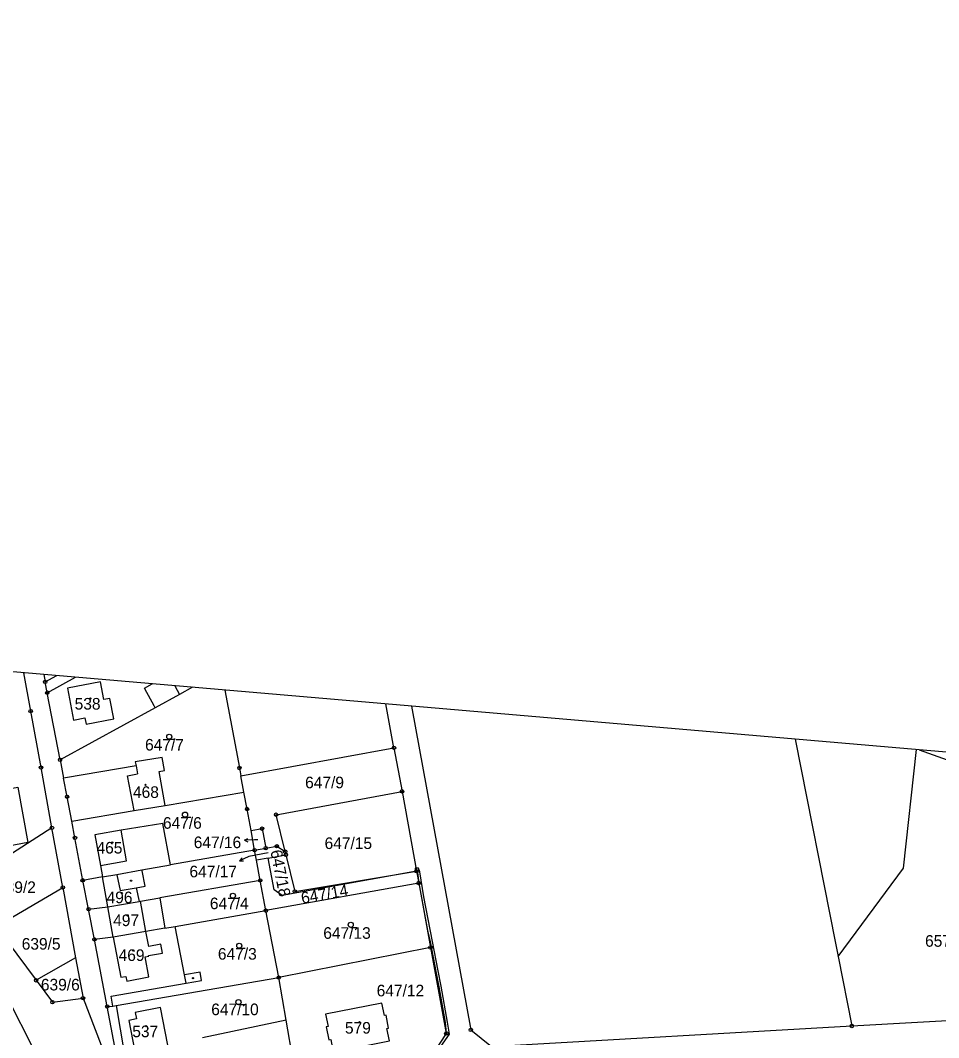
# Model space of a CAD drawing. Extents: x -537341 to -532984, y -1143469 to -1141314.
# Drawn here: x -533804.5 to -533535.5, y -1142913.3 to -1142615.3 of the extents above; entities that cross this region are included whole.
import ezdxf

# ---------------------------------------------------------------- set-up
doc = ezdxf.new("R2010")
doc.units = 0
for name, color, linetype in [('Hranice parcel', 7, 'Continuous'), ('parcelní_č_2000', 7, 'Continuous'), ('Pop  PČ popisy', 7, 'Continuous'), ('Vnitřní kresba', 7, 'Continuous'), ('Věcná břemena k části', 7, 'Continuous'), ('x_formát_rám', 7, 'Continuous'), ('Značky bodu BP', 7, 'Continuous'), ('Značky budov', 7, 'Continuous'), ('Značky kultur', 7, 'Continuous')]:
    doc.layers.add(name, color=color, linetype=linetype)

msp = doc.modelspace()

# ---------------------------------------------------------------- linework, layer by layer
at = {"layer": 'Hranice parcel'}
for p, q in [((-533796.62, -1142812.22), (-533797.23, -1142809.07)), ((-533796.62, -1142812.22), (-533788.31, -1142807.7)), ((-533792.86, -1142831.88), (-533796.62, -1142812.22)), ((-533739.9, -1142836.53), (-533695.03, -1142828.35)), ((-533695.03, -1142828.35), (-533692.68, -1142841.12)), ((-533792.86, -1142831.88), (-533791.82, -1142837.3)), ((-533738.99, -1142841.39), (-533739.9, -1142836.53)), ((-533762.1, -1142845.26), (-533738.99, -1142841.39)), ((-533692.68, -1142841.12), (-533688.43, -1142864.53)), ((-533795.23, -1142851.81), (-533820.96, -1142868.21)), ((-533792.04, -1142869.27), (-533795.23, -1142851.81)), ((-533736.91, -1142852.6), (-533733.68, -1142852.04)), ((-533735.85, -1142858.34), (-533736.91, -1142852.6)), ((-533733.68, -1142852.04), (-533732.6, -1142857.76)), ((-533735.85, -1142858.34), (-533732.6, -1142857.76)), ((-533735.85, -1142858.34), (-533760.5, -1142862.67)), ((-533735.3, -1142861.3), (-533735.85, -1142858.34)), ((-533731.85, -1142860.66), (-533735.3, -1142861.3)), ((-533731.85, -1142860.66), (-533726.7, -1142859.71)), ((-533726.92, -1142858.78), (-533726.7, -1142859.71)), ((-533734.2, -1142867.2), (-533735.3, -1142861.3)), ((-533780.43, -1142866.18), (-533786.23, -1142867.19)), ((-533688.43, -1142864.53), (-533687.8, -1142867.97)), ((-533811.62, -1142880.72), (-533792.04, -1142869.27)), ((-533792.04, -1142869.27), (-533788.29, -1142889.85)), ((-533784.49, -1142875.64), (-533786.23, -1142867.19)), ((-533734.2, -1142867.2), (-533763.65, -1142872.3)), ((-533732.56, -1142876.06), (-533734.2, -1142867.2)), ((-533687.8, -1142867.97), (-533732.56, -1142876.06)), ((-533687.8, -1142867.97), (-533684.34, -1142886.86)), ((-533763.65, -1142872.3), (-533762.13, -1142881.2)), ((-533782.79, -1142884.49), (-533784.49, -1142875.64)), ((-533759.14, -1142880.69), (-533732.56, -1142876.06)), ((-533728.79, -1142895.67), (-533732.56, -1142876.06)), ((-533811.62, -1142880.72), (-533799.87, -1142896.47)), ((-533762.13, -1142881.2), (-533759.14, -1142880.69)), ((-533779.04, -1142904.13), (-533782.79, -1142884.49)), ((-533684.34, -1142886.86), (-533728.79, -1142895.67)), ((-533788.29, -1142889.85), (-533799.87, -1142896.47)), ((-533788.29, -1142889.85), (-533786.13, -1142901.71)), ((-533564.92, -1142889.45), (-533560.9, -1142909.85)), ((-533776.44, -1142903.87), (-533728.79, -1142895.67)), ((-533726.64, -1142908.16), (-533728.79, -1142895.67)), ((-533800.6, -1142916.51), (-533807.97, -1142902.05)), ((-533786.13, -1142901.71), (-533773.02, -1142935.56)), ((-533779.04, -1142904.13), (-533777.37, -1142904.03)), ((-533773.02, -1142935.56), (-533779.04, -1142904.13)), ((-533777.37, -1142904.03), (-533776.44, -1142903.87)), ((-533776.44, -1142903.87), (-533774.1, -1142917.72)), ((-533726.64, -1142908.16), (-533751.13, -1142913.35)), ((-533724.28, -1142921.87), (-533726.64, -1142908.16)), ((-533666.46, -1142915.84), (-533560.9, -1142909.85))]:
    msp.add_line(p, q, dxfattribs=at)
for points in [[(-533795.23, -1142851.81), (-533798.44, -1142834.16), (-533801.46, -1142817.62), (-533803.51, -1142806.39)], [(-533797.62, -1142806.9), (-533797.23, -1142809.07)], [(-533797.23, -1142809.07), (-533793.84, -1142807.22)], [(-533788.96, -1142820.23), (-533785.58, -1142819.61), (-533785.25, -1142821.4), (-533777.09, -1142819.9), (-533778.24, -1142813.91), (-533780.04, -1142814.26), (-533781.05, -1142809.01), (-533790.71, -1142810.87), (-533788.96, -1142820.23)], [(-533754.04, -1142810.65), (-533757.82, -1142812.71), (-533764.99, -1142816.64), (-533792.86, -1142831.88)], [(-533744.55, -1142811.46), (-533740.32, -1142834.27), (-533739.9, -1142836.53)], [(-533695.03, -1142828.35), (-533697.39, -1142815.52)], [(-533689.87, -1142816.17), (-533672.51, -1142910.99), (-533666.46, -1142915.84)], [(-533577.47, -1142825.84), (-533565.69, -1142885.58), (-533564.92, -1142889.45)], [(-533564.92, -1142889.45), (-533545.8, -1142863.64), (-533541.96, -1142828.89)], [(-533541.19, -1142828.96), (-533520.36, -1142836.42)], [(-533770.81, -1142832.48), (-533770.59, -1142833.65), (-533791.23, -1142837.2), (-533791.82, -1142837.3)], [(-533762.3, -1142835.05), (-533762.98, -1142831.19), (-533770.81, -1142832.48)], [(-533762.1, -1142845.26), (-533763.86, -1142835.28), (-533762.3, -1142835.05)], [(-533805.2, -1142839.88), (-533802.28, -1142856.11), (-533811.64, -1142857.9), (-533814.72, -1142841.68), (-533805.2, -1142839.88)], [(-533789.43, -1142849.83), (-533790.79, -1142842.7), (-533791.82, -1142837.3)], [(-533736.91, -1142852.6), (-533738.08, -1142846.3), (-533738.99, -1142841.39)], [(-533726.92, -1142858.78), (-533729.57, -1142847.95), (-533692.68, -1142841.12)], [(-533789.43, -1142849.83), (-533771.19, -1142846.77), (-533762.1, -1142845.26)], [(-533786.23, -1142867.19), (-533788.49, -1142854.75), (-533789.43, -1142849.83)], [(-533760.5, -1142862.67), (-533762.76, -1142850.54), (-533774.98, -1142852.53), (-533782.64, -1142853.88), (-533781.03, -1142862.83), (-533780.43, -1142866.18)], [(-533732.6, -1142857.76), (-533729.33, -1142857.2), (-533726.92, -1142858.78)], [(-533688.43, -1142864.53), (-533727.78, -1142871.62), (-533730.11, -1142870.01), (-533731.85, -1142860.66)], [(-533726.7, -1142859.71), (-533724.08, -1142870.42), (-533688.43, -1142864.53)], [(-533780.43, -1142866.18), (-533776.23, -1142865.44), (-533768.87, -1142864.14), (-533760.5, -1142862.67)], [(-533784.49, -1142875.64), (-533778.85, -1142874.97), (-533769.73, -1142873.35), (-533769.31, -1142873.28), (-533763.65, -1142872.3)], [(-533762.13, -1142881.2), (-533767.72, -1142882.16), (-533777.26, -1142883.85), (-533782.79, -1142884.49)], [(-533777.37, -1142904.03), (-533777.91, -1142901.1), (-533755.93, -1142897.31), (-533751.39, -1142896.53), (-533751.81, -1142894.06), (-533756.41, -1142894.82), (-533759.14, -1142880.69)], [(-533684.34, -1142886.86), (-533679.73, -1142912.01), (-533683.69, -1142917.96)], [(-533799.87, -1142896.47), (-533795.09, -1142902.87), (-533786.13, -1142901.71)], [(-533761.27, -1142915.51), (-533763.48, -1142904.48), (-533770.82, -1142905.89), (-533770.44, -1142907.79), (-533772.69, -1142908.22), (-533770.94, -1142917.31)], [(-533714.09, -1142913.89), (-533713.58, -1142913.79), (-533712.81, -1142917.52), (-533696.39, -1142914.21), (-533697.12, -1142910.54), (-533696.62, -1142910.44), (-533697.36, -1142906.7), (-533697.86, -1142906.8), (-533698.59, -1142903.13), (-533715.11, -1142906.43), (-533714.36, -1142910.04), (-533714.86, -1142910.14), (-533714.09, -1142913.89)], [(-533560.9, -1142909.85), (-533520.72, -1142907.57)]]:
    msp.add_lwpolyline(points, dxfattribs=at)
at = {"layer": 'Pop  PČ popisy'}
for p, q in [((-533738.87, -1142855.45), (-533737.89, -1142854.91)), ((-533735.87, -1142855.34), (-533738.87, -1142855.45)), ((-533738.87, -1142855.45), (-533737.85, -1142855.91)), ((-533734.9, -1142855.31), (-533735.87, -1142855.34)), ((-533737.52, -1142860.24), (-533740.26, -1142861.46)), ((-533740.26, -1142861.46), (-533739.55, -1142860.6)), ((-533731.89, -1142859.17), (-533737.52, -1142860.24)), ((-533740.26, -1142861.46), (-533739.14, -1142861.51))]:
    msp.add_line(p, q, dxfattribs=at)
at = {"layer": 'Vnitřní kresba'}
for p, q in [((-533768.16, -1142810.85), (-533765.92, -1142809.62)), ((-533759.19, -1142810.2), (-533757.82, -1142812.71)), ((-533768.02, -1142811.11), (-533768.16, -1142810.85)), ((-533765.33, -1142816.03), (-533768.02, -1142811.11)), ((-533764.99, -1142816.64), (-533765.33, -1142816.03)), ((-533770.59, -1142833.65), (-533770.15, -1142836.03)), ((-533773.07, -1142836.56), (-533770.15, -1142836.03)), ((-533771.19, -1142846.77), (-533773.07, -1142836.56)), ((-533773.4, -1142861.49), (-533774.98, -1142852.53)), ((-533781.03, -1142862.83), (-533773.4, -1142861.49)), ((-533778.85, -1142874.97), (-533780.43, -1142866.18)), ((-533776.23, -1142865.44), (-533776.2, -1142865.61)), ((-533776.2, -1142865.61), (-533775.29, -1142870.2)), ((-533768.81, -1142864.42), (-533768.87, -1142864.14)), ((-533767.91, -1142868.93), (-533768.81, -1142864.42)), ((-533775.29, -1142870.2), (-533770.6, -1142869.39)), ((-533770.6, -1142869.39), (-533767.91, -1142868.93)), ((-533770.6, -1142869.39), (-533769.73, -1142873.35)), ((-533777.26, -1142883.85), (-533778.85, -1142874.97)), ((-533767.72, -1142882.16), (-533769.31, -1142873.28)), ((-533777.26, -1142883.85), (-533775.06, -1142895.58)), ((-533766.89, -1142886.53), (-533767.72, -1142882.16)), ((-533763.32, -1142885.89), (-533766.89, -1142886.53)), ((-533762.86, -1142888.47), (-533763.32, -1142885.89)), ((-533767.92, -1142889.62), (-533766.88, -1142889.43)), ((-533766.86, -1142895.46), (-533767.92, -1142889.62)), ((-533766.92, -1142889.2), (-533762.86, -1142888.47)), ((-533766.88, -1142889.43), (-533766.92, -1142889.2)), ((-533775.06, -1142895.58), (-533773.6, -1142895.31)), ((-533773.6, -1142895.31), (-533773.34, -1142896.67)), ((-533773.34, -1142896.67), (-533766.86, -1142895.46)), ((-533755.93, -1142897.31), (-533756.41, -1142894.82))]:
    msp.add_line(p, q, dxfattribs=at)
at = {"layer": 'Věcná břemena k části'}
msp.add_lwpolyline([(-533688.83, -1142863.58), (-533688.85, -1142864.28), (-533688.47, -1142864.29), (-533688.6, -1142863.59)], close=True, dxfattribs=at)
msp.add_lwpolyline([(-533682.63, -1142917.83), (-533678.79, -1142912.25), (-533679.38, -1142908.68), (-533681.25, -1142898.22), (-533682.07, -1142893.73), (-533683.71, -1142885.09), (-533686.29, -1142872.06), (-533687.49, -1142864.72), (-533687.87, -1142863.61), (-533688.6, -1142863.59), (-533688.47, -1142864.29), (-533688.17, -1142864.89), (-533687.8, -1142867.97), (-533685.25, -1142881.88), (-533684.39, -1142885.23), (-533682.75, -1142893.85), (-533681.93, -1142898.34), (-533680.06, -1142908.8), (-533679.73, -1142912.01), (-533683.69, -1142917.96)], dxfattribs=at)
at = {"layer": 'x_formát_rám'}
msp.add_line((-533104.67, -1142866.51), (-536024.88, -1142615.28), dxfattribs=at)
at = {"layer": 'Značky bodu BP'}
for centre, radius in [((-533797.23, -1142809.07), 0.5), ((-533797.23, -1142809.07), 0.0303), ((-533796.62, -1142812.22), 0.5), ((-533796.62, -1142812.22), 0.0303), ((-533801.46, -1142817.62), 0.5), ((-533801.46, -1142817.62), 0.0303), ((-533695.03, -1142828.35), 0.5), ((-533695.03, -1142828.35), 0.0303), ((-533798.44, -1142834.16), 0.5), ((-533792.86, -1142831.88), 0.5), ((-533792.86, -1142831.88), 0.0303), ((-533740.32, -1142834.27), 0.5), ((-533798.44, -1142834.16), 0.0303), ((-533740.32, -1142834.27), 0.0303), ((-533790.79, -1142842.7), 0.5), ((-533790.79, -1142842.7), 0.0303), ((-533692.68, -1142841.12), 0.5), ((-533692.68, -1142841.12), 0.0303), ((-533738.08, -1142846.3), 0.5), ((-533738.08, -1142846.3), 0.0303), ((-533729.57, -1142847.95), 0.5), ((-533729.57, -1142847.95), 0.0303), ((-533795.23, -1142851.81), 0.5), ((-533795.23, -1142851.81), 0.0303), ((-533733.68, -1142852.04), 0.5), ((-533788.49, -1142854.75), 0.5), ((-533788.49, -1142854.75), 0.0303), ((-533733.68, -1142852.04), 0.0303), ((-533735.85, -1142858.34), 0.5), ((-533732.6, -1142857.76), 0.5), ((-533732.6, -1142857.76), 0.0303), ((-533729.33, -1142857.2), 0.5), ((-533729.33, -1142857.2), 0.0303), ((-533735.85, -1142858.34), 0.0303), ((-533726.92, -1142858.78), 0.5), ((-533726.7, -1142859.71), 0.5), ((-533726.92, -1142858.78), 0.0303), ((-533726.7, -1142859.71), 0.0303), ((-533786.23, -1142867.19), 0.5), ((-533734.2, -1142867.2), 0.5), ((-533688.43, -1142864.53), 0.5), ((-533688.43, -1142864.53), 0.0303), ((-533792.04, -1142869.27), 0.5), ((-533792.04, -1142869.27), 0.0303), ((-533786.23, -1142867.19), 0.0303), ((-533734.2, -1142867.2), 0.0303), ((-533687.8, -1142867.97), 0.5), ((-533687.8, -1142867.97), 0.0303), ((-533724.08, -1142870.42), 0.5), ((-533724.08, -1142870.42), 0.0303), ((-533784.49, -1142875.64), 0.5), ((-533784.49, -1142875.64), 0.0303), ((-533732.56, -1142876.06), 0.5), ((-533732.56, -1142876.06), 0.0303), ((-533782.79, -1142884.49), 0.5), ((-533782.79, -1142884.49), 0.0303), ((-533684.34, -1142886.86), 0.5), ((-533684.34, -1142886.86), 0.0303), ((-533799.87, -1142896.47), 0.5), ((-533799.87, -1142896.47), 0.0303), ((-533728.79, -1142895.67), 0.5), ((-533728.79, -1142895.67), 0.0303), ((-533795.09, -1142902.87), 0.5), ((-533786.13, -1142901.71), 0.5), ((-533786.13, -1142901.71), 0.0303), ((-533795.09, -1142902.87), 0.0303), ((-533779.04, -1142904.13), 0.5), ((-533779.04, -1142904.13), 0.0303), ((-533679.73, -1142912.01), 0.5), ((-533672.51, -1142910.99), 0.5), ((-533672.51, -1142910.99), 0.0303), ((-533560.9, -1142909.85), 0.5), ((-533560.9, -1142909.85), 0.0303), ((-533679.73, -1142912.01), 0.0303)]:
    msp.add_circle(centre, radius, dxfattribs=at)
at = {"layer": 'Značky budov'}
for centre in [(-533783.98, -1142813.91), (-533767.83, -1142839.21), (-533777.55, -1142856.12), (-533772.05, -1142867.3), (-533774.78, -1142870.9), (-533773.06, -1142877.46), (-533771.4, -1142887.74), (-533753.9, -1142895.82), (-533705.14, -1142908.72), (-533767.61, -1142909.89)]:
    msp.add_circle(centre, 0.175, dxfattribs=at)
at = {"layer": 'Značky kultur'}
for p, q in [((-533760.86, -1142825.88), (-533759.11, -1142825.88)), ((-533756.25, -1142848.7), (-533754.5, -1142848.7)), ((-533742.21, -1142872.45), (-533740.46, -1142872.45)), ((-533707.71, -1142880.96), (-533705.96, -1142880.96)), ((-533740.36, -1142887.08), (-533738.61, -1142887.08)), ((-533740.6, -1142903.59), (-533738.85, -1142903.59))]:
    msp.add_line(p, q, dxfattribs=at)
for centre in [(-533760.86, -1142825.13), (-533756.25, -1142847.95), (-533742.21, -1142871.7), (-533707.71, -1142880.21), (-533740.36, -1142886.33), (-533740.6, -1142902.84)]:
    msp.add_circle(centre, 0.75, dxfattribs=at)

# ---------------------------------------------------------------- texts
at = {"layer": 'parcelní_č_2000'}
for s, p in [('538', (-533788.58, -1142817.17)), ('647/7', (-533767.95, -1142829.17)), ('647/9', (-533721.06, -1142840.22)), ('468', (-533771.49, -1142843.04)), ('647/6', (-533762.71, -1142852.07)), ('647/16', (-533753.7, -1142857.76)), ('647/15', (-533715.36, -1142858.01)), ('465', (-533782.18, -1142859.34)), ('647/17', (-533754.95, -1142866.3)), ('639/2', (-533811.32, -1142870.89)), ('496', (-533779.23, -1142873.89)), ('647/4', (-533748.97, -1142875.64)), ('497', (-533777.31, -1142880.59)), ('647/13', (-533715.74, -1142884.31)), ('639/5', (-533804.09, -1142887.49)), ('657/3', (-533539.45, -1142886.63)), ('469', (-533775.7, -1142890.8)), ('647/3', (-533746.62, -1142890.42)), ('639/6', (-533798.47, -1142899.44)), ('647/12', (-533700.1, -1142901.17)), ('647/10', (-533748.57, -1142906.68)), ('537', (-533771.7, -1142913.13)), ('579', (-533709.39, -1142912.08))]:
    msp.add_text(s, height=3.4, dxfattribs=at).set_placement(p)
for s, rotation, p in [('647/18', 281, (-533731.26, -1142858.59)), ('647/14', 10, (-533721.94, -1142874.09))]:
    msp.add_text(s, height=3.4, rotation=rotation, dxfattribs=at).set_placement(p)

doc.saveas('drawing.dxf')
